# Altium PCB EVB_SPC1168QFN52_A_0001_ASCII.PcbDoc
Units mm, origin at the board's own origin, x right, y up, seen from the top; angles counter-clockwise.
Board outline 65.1 x 66.6 mm, 2 copper layers (Top Layer, Bottom Layer); 106 components, 105 nets, 333 pads, 121 vias.
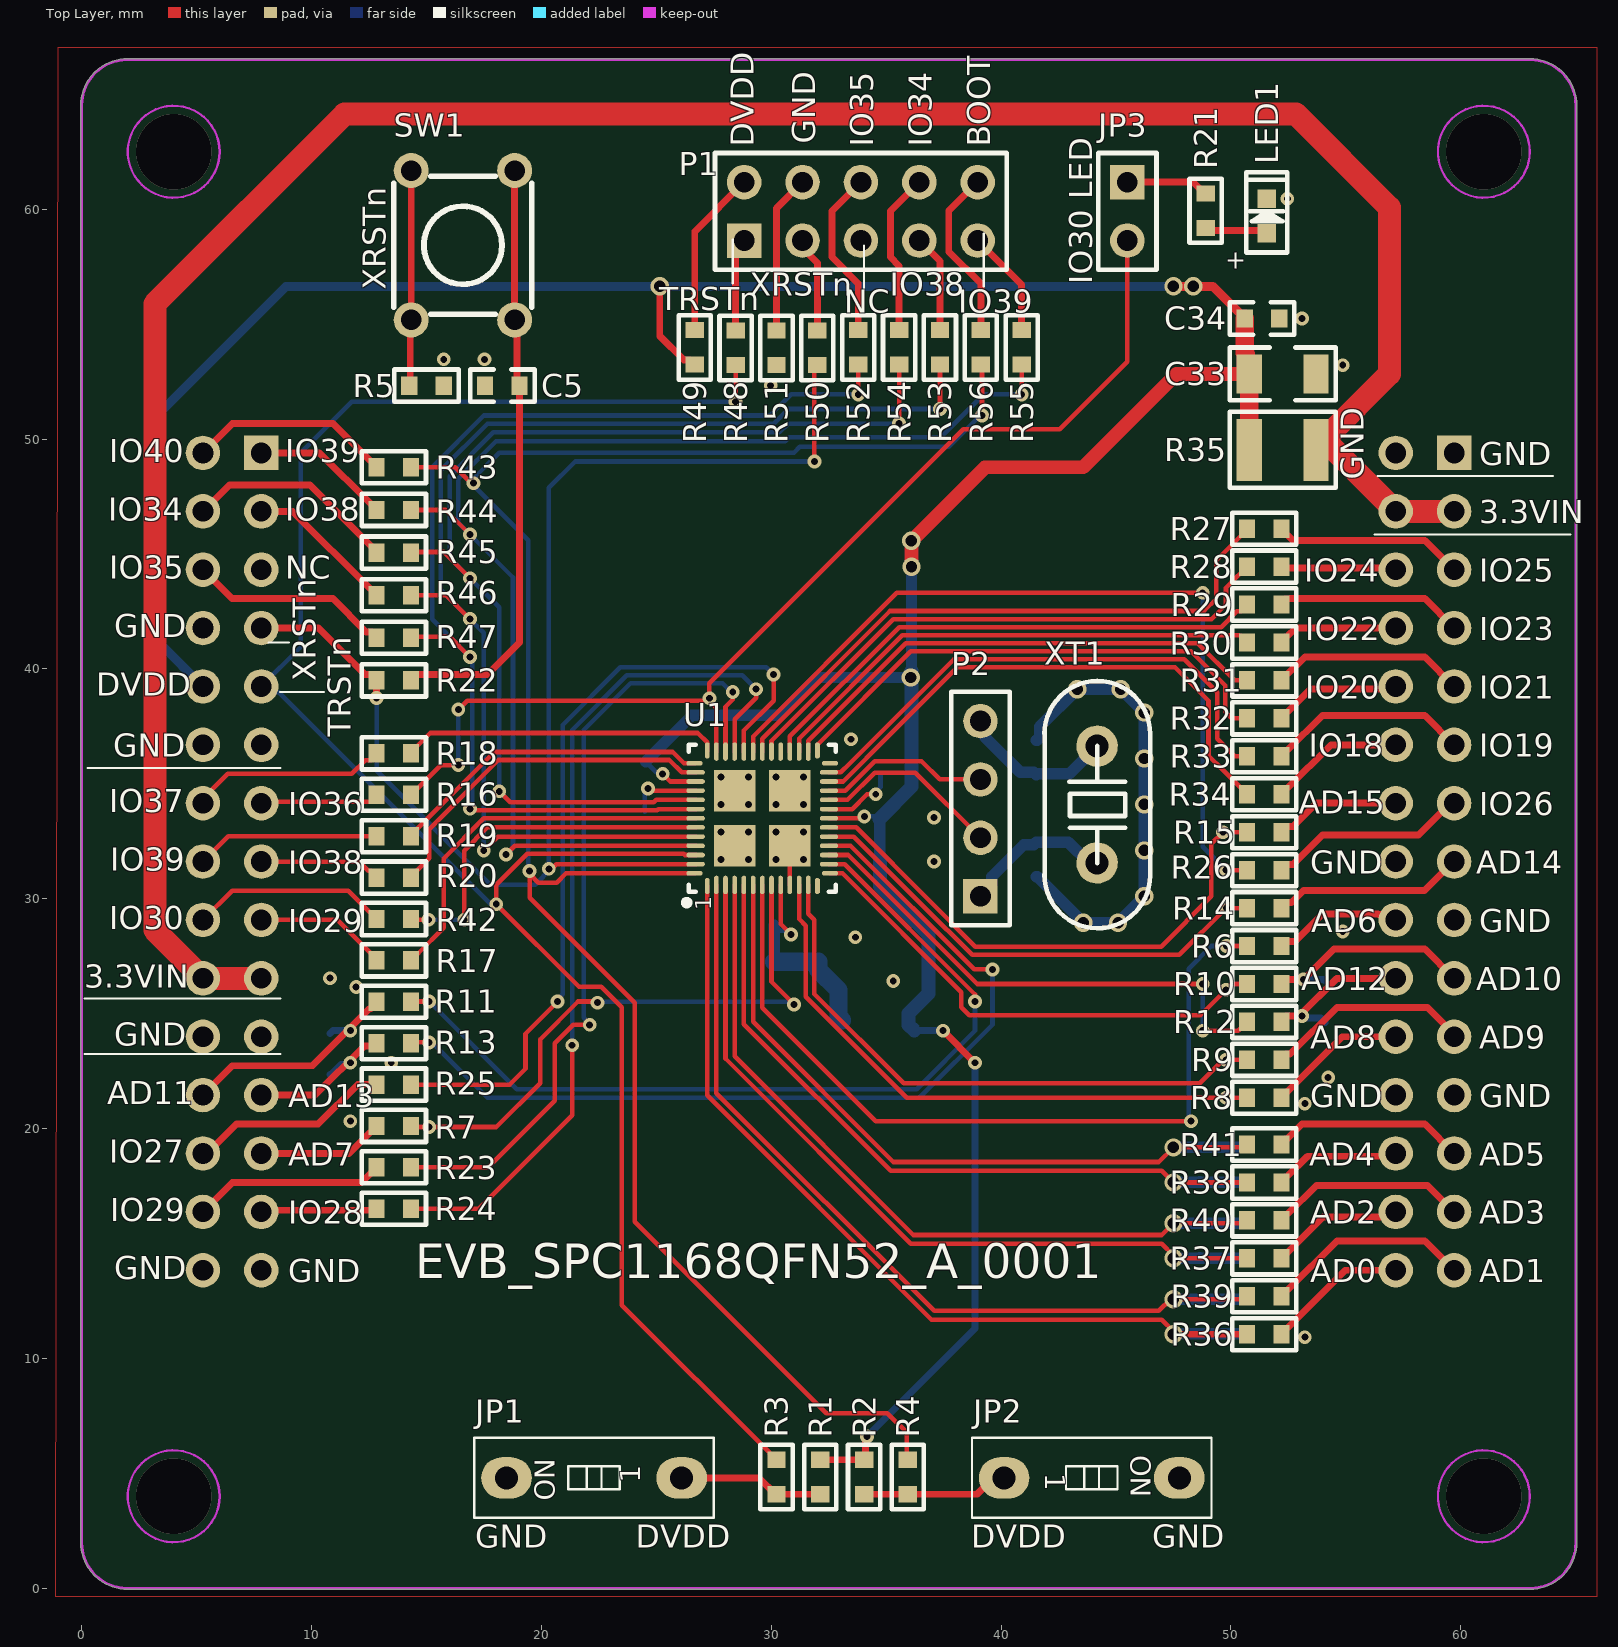
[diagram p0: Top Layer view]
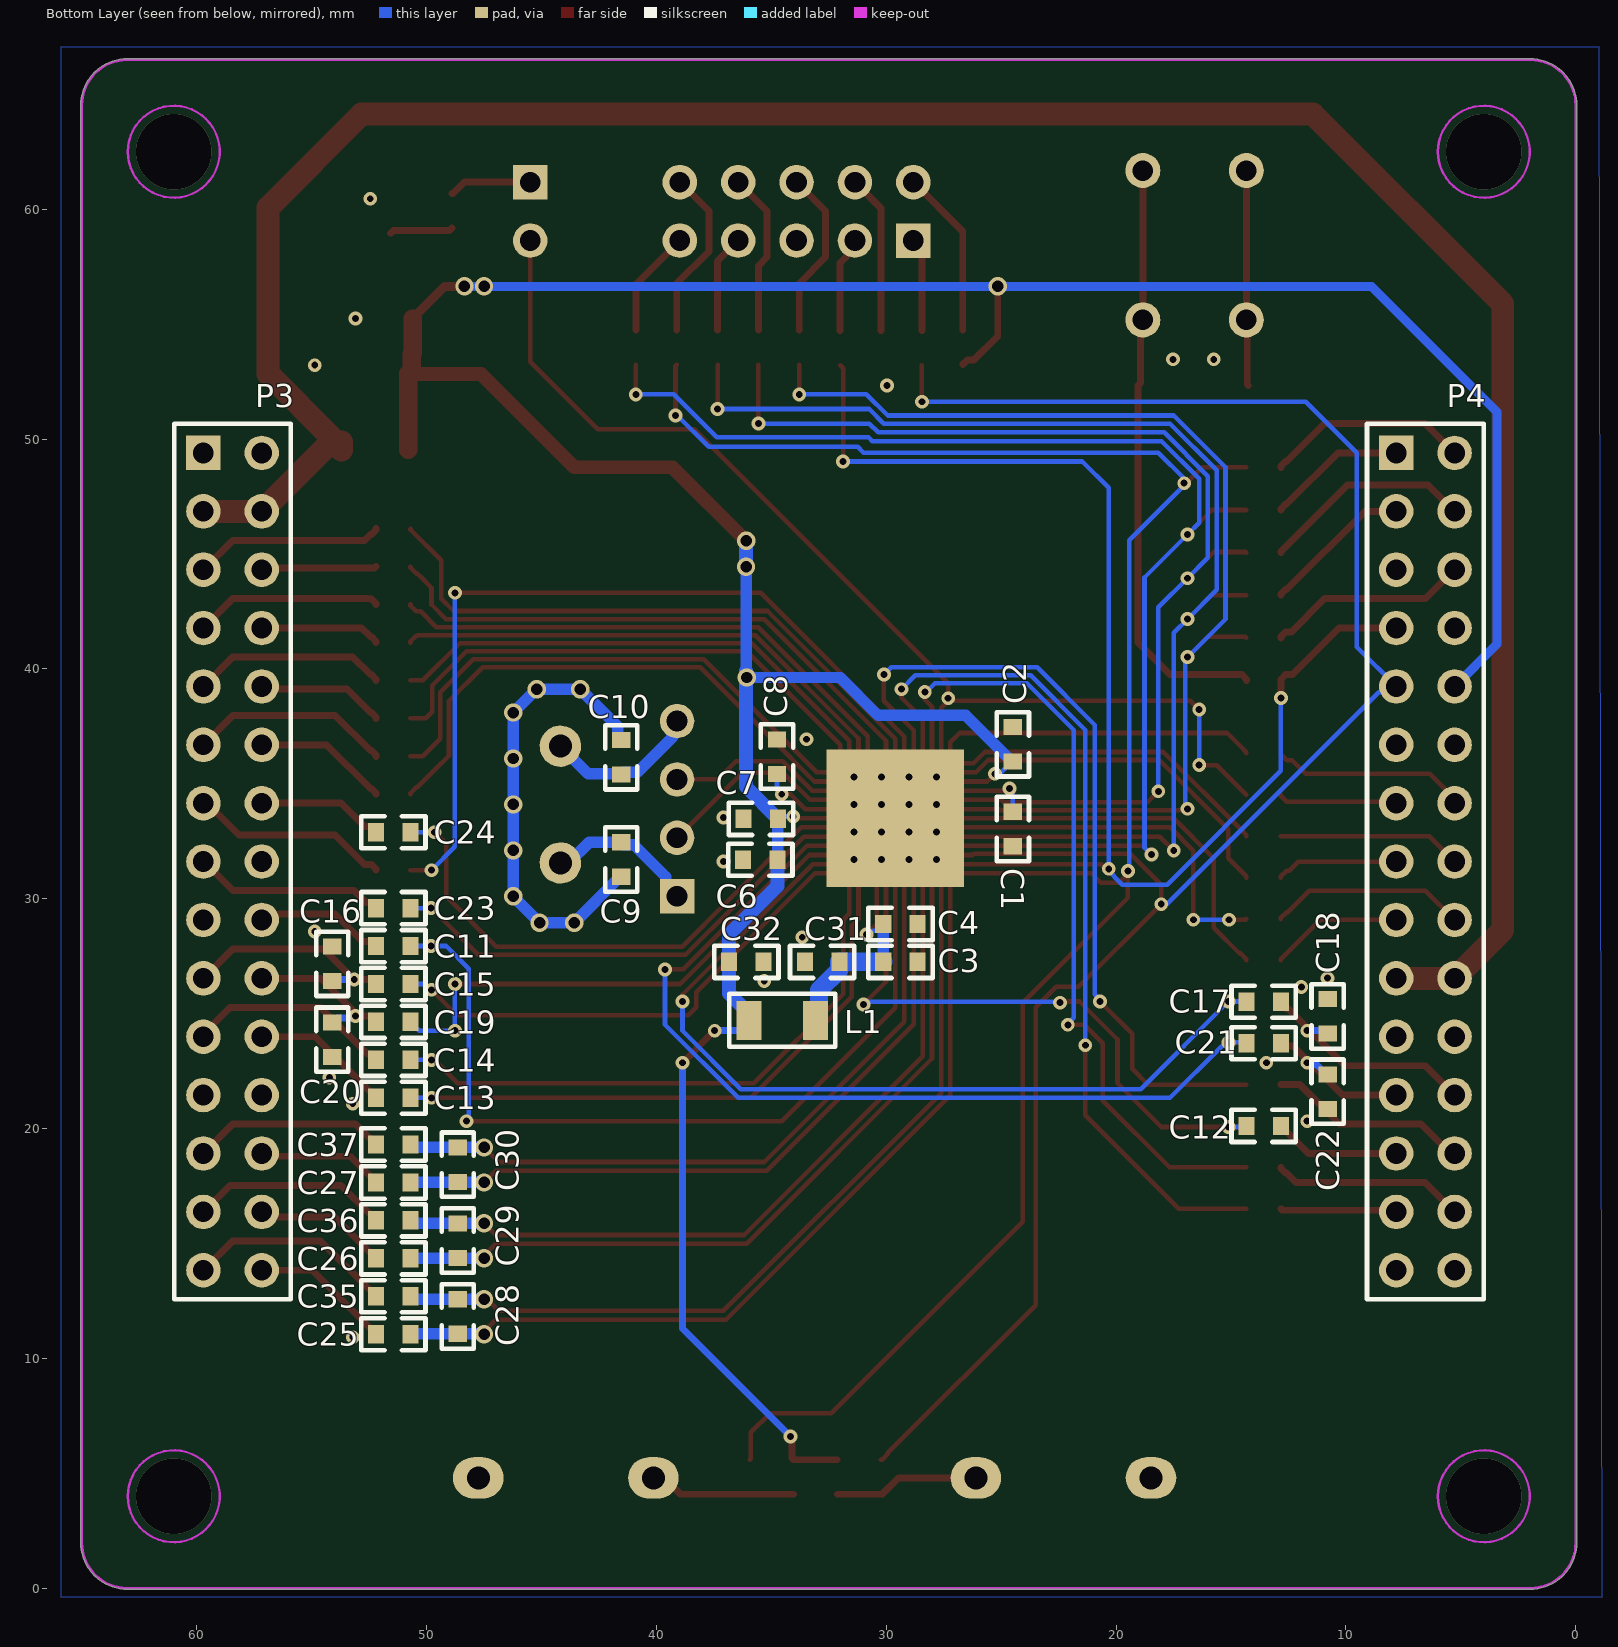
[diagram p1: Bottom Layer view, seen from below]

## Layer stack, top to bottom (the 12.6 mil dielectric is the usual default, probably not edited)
Top Solder: solder mask 0.0102, Solder Resist, Dk 3.5
Top Layer: signal copper 0.0356
Dielectric 1: dielectric 0.32, FR-4, Dk 4.8
Bottom Layer: signal copper 0.0356
Bottom Solder: solder mask 0.0102, Solder Resist, Dk 3.5

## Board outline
-0.05,2 ccw(c2,2) 2,-0.05 ccw(c2,0) 2.016,-0.048 ccw(c2.032,0) 2.032,-0.05 62.992,-0.05 ccw(c62.992,0) 62.996,-0.05 ccw(c63,0) 63,-0.05 ccw(c63,2) 65.05,2 ccw(c65,2) 65.05,2.004 ccw(c65,2.008) 65.05,2.008 65.05,64.5 ccw(c63,64.5) 63,66.55 2,66.55 ccw(c2,64.5) -0.05,64.5 -0.05,2.032 ccw(c0,2.032) -0.048,2.016 ccw(c0,2)

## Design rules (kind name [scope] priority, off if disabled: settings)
AssemblyTestPointUsage [All] p0: scope1count=1 scope1_0_kind=Board scope1_0_value=Board scope2count=1 scope2_0_kind=Board scope2_0_value=Board commentlength=0
AssemblyTestpoint [All] p0: scope1count=1 scope1_0_kind=Board scope1_0_value=Board scope2count=1 scope2_0_kind=Board scope2_0_value=Board commentlength=0
Clearance [All] p0: scope1count=1 scope1_0_kind=Board scope1_0_value=Board scope2count=1 scope2_0_kind=Board scope2_0_value=Board commentlength=0 gap=0.2
Clearance [All] p1: gap=0.2 ignorepadtopadclearanceinfootprint=FALSE except(0: Arc-Hole Track-Hole SMDPad-Hole THPad-Hole Via-Hole Fill-Hole Poly-Hole Region-Hole Text-Hole; 0.15: Arc-Arc Arc-Track Track-Track)
ComponentClearance [All] p0: scope1count=1 scope1_0_kind=Board scope1_0_value=Board scope2count=1 scope2_0_kind=Board scope2_0_value=Board commentlength=0 gap=0.254 collisioncheckmode=3
DiffPairsRouting [All] p0: scope1count=1 scope1_0_kind=Board scope1_0_value=Board scope2count=1 scope2_0_kind=Board scope2_0_value=Board commentlength=0
FabricationTestPointUsage [All] p0: scope1count=1 scope1_0_kind=Board scope1_0_value=Board scope2count=1 scope2_0_kind=Board scope2_0_value=Board commentlength=0 valid=0 allowmultiple=FALSE
FabricationTestpoint [All] p0: scope1count=1 scope1_0_kind=Board scope1_0_value=Board scope2count=1 scope2_0_kind=Board scope2_0_value=Board commentlength=0 side=3 testpointundercomponent=TRUE minsize=1.016 maxsize=2.54 preferedsize=1.524 minholesize=0 maxholesize=1.016 preferedholesize=0.813 testpointgrid=0.025
FanoutControl Fanout_BGA [All] p0 off: scope1count=1 scope1_0_kind=Board scope1_0_value=Board scope2count=1 scope2_0_kind=Board scope2_0_value=Board commentlength=69 // Protel DXP Scope 1 Expression Was: IsBGA   Fanout_BGA (Default Rule)
FanoutControl Fanout_LCC [All] p0 off: scope1count=1 scope1_0_kind=Board scope1_0_value=Board scope2count=1 scope2_0_kind=Board scope2_0_value=Board commentlength=69 // Protel DXP Scope 1 Expression Was: IsLCC   Fanout_LCC (Default Rule)
FanoutControl Fanout_SOIC [All] p0 off: scope1count=1 scope1_0_kind=Board scope1_0_value=Board scope2count=1 scope2_0_kind=Board scope2_0_value=Board commentlength=71 // Protel DXP Scope 1 Expression Was: IsSOIC   Fanout_SOIC (Default Rule)
FanoutControl Fanout_Small [All] p0 off: scope1count=1 scope1_0_kind=Board scope1_0_value=Board scope2count=1 scope2_0_kind=Board scope2_0_value=Board commentlength=84 // Protel DXP Scope 1 Expression Was: (CompPinCount < 5)   Fanout_Small (Default Rule)
FanoutControl Fanout_Default [All] p0: scope1count=1 scope1_0_kind=Board scope1_0_value=Board scope2count=1 scope2_0_kind=Board scope2_0_value=Board commentlength=30 // Fanout_Default (Default Rule)
Height [All] p0: scope1count=1 scope1_0_kind=Board scope1_0_value=Board scope2count=1 scope2_0_kind=Board scope2_0_value=Board commentlength=0
HoleSize [All] p0: scope1count=1 scope1_0_kind=Board scope1_0_value=Board scope2count=1 scope2_0_kind=Board scope2_0_value=Board commentlength=0 absolutevalues=TRUE maxlimit=2.54 minlimit=0.025 maxpercent=80.000 minpercent=20.000
HoleToHoleClearance [All] p0: scope1count=1 scope1_0_kind=Board scope1_0_value=Board scope2count=1 scope2_0_kind=Board scope2_0_value=Board commentlength=0
LayerPairs [All] p0: scope1count=1 scope1_0_kind=Board scope1_0_value=Board scope2count=1 scope2_0_kind=Board scope2_0_value=Board commentlength=0 enforce=TRUE
MinimumSolderMaskSliver [All] p0: scope1count=1 scope1_0_kind=Board scope1_0_value=Board scope2count=1 scope2_0_kind=Board scope2_0_value=Board commentlength=0
NetAntennae [All] p0: scope1count=1 scope1_0_kind=Board scope1_0_value=Board scope2count=1 scope2_0_kind=Board scope2_0_value=Board commentlength=0
PasteMaskExpansion [All] p0: scope1count=1 scope1_0_kind=Board scope1_0_value=Board scope2count=1 scope2_0_kind=Board scope2_0_value=Board commentlength=0 expansion=0
PlaneClearance [All] p0: scope1count=1 scope1_0_kind=Board scope1_0_value=Board scope2count=1 scope2_0_kind=Board scope2_0_value=Board commentlength=0 clearance=0.508
PlaneConnect [All] p0: scope1count=1 scope1_0_kind=Board scope1_0_value=Board scope2count=1 scope2_0_kind=Board scope2_0_value=Board commentlength=0 planeconnectstyle=Direct reliefexpansion=0.508 reliefentries=4 reliefconductorwidth=0.254 reliefairgap=0.254
PlaneConnect [All] p1: planeconnectstyle=Direct reliefexpansion=0.508 reliefentries=4 reliefconductorwidth=0.254 reliefairgap=0.254
PolygonConnect [All] p0: scope1count=1 scope1_0_kind=Board scope1_0_value=Board scope2count=1 scope2_0_kind=Board scope2_0_value=Board commentlength=0 connectstyle=Direct reliefconductorwidth=0.254 reliefentries=4 polygonreliefangle="90 Angle"
PolygonConnect [All] p1: connectstyle=Direct reliefconductorwidth=0.254 reliefentries=4 polygonreliefangle="90 Angle" airgapwidth=0.254
RoutingCorners [All] p0: scope1count=1 scope1_0_kind=Board scope1_0_value=Board scope2count=1 scope2_0_kind=Board scope2_0_value=Board commentlength=0 cornerstyle=45-Degree minsetback=2.54 maxsetback=2.54
RoutingLayers [All] p0: scope1count=1 scope1_0_kind=Board scope1_0_value=Board scope2count=1 scope2_0_kind=Board scope2_0_value=Board commentlength=0 top layer=Automatic bottom layer=Automatic
RoutingPriority [All] p0: scope1count=1 scope1_0_kind=Board scope1_0_value=Board scope2count=1 scope2_0_kind=Board scope2_0_value=Board commentlength=0
RoutingTopology [All] p0: scope1count=1 scope1_0_kind=Board scope1_0_value=Board scope2count=1 scope2_0_kind=Board scope2_0_value=Board commentlength=0 topology=Shortest
RoutingVias [All] p0: scope1count=1 scope1_0_kind=Board scope1_0_value=Board scope2count=1 scope2_0_kind=Board scope2_0_value=Board commentlength=0 holewidth=0.711 width=1.27 viastyle="Through Hole" minholewidth=0.711 minwidth=1.27 maxholewidth=4 maxwidth=4
RoutingVias [All] p1: holewidth=0.711 width=1.27 viastyle="Through Hole" minholewidth=0.711 minwidth=1.27 maxholewidth=4 maxwidth=4
ShortCircuit [All] p0: scope1count=1 scope1_0_kind=Board scope1_0_value=Board scope2count=1 scope2_0_kind=Board scope2_0_value=Board commentlength=0 allowed=FALSE
SilkToBoardRegionClearance [All] p0: scope1count=1 scope1_0_kind=Board scope1_0_value=Board scope2count=1 scope2_0_kind=Board scope2_0_value=Board commentlength=0
SilkToSilkClearance [All] p0: scope1count=1 scope1_0_kind=Board scope1_0_value=Board scope2count=1 scope2_0_kind=Board scope2_0_value=Board commentlength=0
SilkToSolderMaskClearance [All] p0 off: scope1count=1 scope1_0_kind=Board scope1_0_value=Board scope2count=1 scope2_0_kind=Board scope2_0_value=Board commentlength=44 // Protel DXP Scope 1 Expression Was: IsPad
SolderMaskExpansion [All] p0: scope1count=1 scope1_0_kind=Board scope1_0_value=Board scope2count=1 scope2_0_kind=Board scope2_0_value=Board commentlength=0 expansion=0.102
SolderMaskExpansion [All] p1: expansion=0.102 istentingtop=FALSE
UnRoutedNet [All] p0: scope1count=1 scope1_0_kind=Board scope1_0_value=Board scope2count=1 scope2_0_kind=Board scope2_0_value=Board commentlength=0
UnpouredPolygon [All] p0: scope1count=1 scope1_0_kind=Board scope1_0_value=Board scope2count=1 scope2_0_kind=Board scope2_0_value=Board commentlength=0
Width [All] p0: scope1count=1 scope1_0_kind=Board scope1_0_value=Board scope2count=1 scope2_0_kind=Board scope2_0_value=Board commentlength=0 maxlimit=3 minlimit=0.15 preferedwidth=0.254
Width [All] p1: maxlimit=3 minlimit=0.15 preferedwidth=0.254 minimp=50.000000 maximp=50.000000 favimp=50.000000
29 further rules are at their usual default settings.

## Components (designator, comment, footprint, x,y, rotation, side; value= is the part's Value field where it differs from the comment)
C1 "100nF" 0603C 24.487,32.282 r90 bottom
C2 "100nF" 0603C 24.487,37.465 r270 bottom
C3 "4.7uF" 0603C 28.631,27.249 r0 bottom
C4 "100nF" 0603C 28.631,28.9 r0 bottom
C5 "1uF" 0603C 17.55,52.324 r0 top
C6 "4.7uF" 0603C 36.227,31.694 r180 bottom
C7 "100nF" 0603C 36.203,33.472 r180 bottom
C8 "2.2uF" 0603C 34.753,36.933 r270 bottom
C9 "20pF" 0603C 41.529,30.956 r90 bottom
C10 "20pF" 0603C 41.529,36.901 r270 bottom
C11 "100pF" 0603C 50.697,27.94 r0 bottom
C12 "100pF" 0603C 14.327,20.112 r180 bottom
C13 "100pF" 0603C 50.697,21.336 r0 bottom
C14 "100pF" 0603C 50.697,22.987 r0 bottom
C15 "100pF" 0603C 50.697,26.289 r0 bottom
C16 "100pF" 0603C 54.102,27.916 r270 bottom
C17 "100pF" 0603C 14.327,25.515 r180 bottom
C18 "100pF" 0603C 10.795,25.63 r270 bottom
C19 "100pF" 0603C 50.697,24.638 r0 bottom
C20 "100pF" 0603C 54.102,23.114 r90 bottom
C21 "100pF" 0603C 14.327,23.714 r180 bottom
C22 "100pF" 0603C 10.795,20.852 r90 bottom
C23 "100pF" 0603C 50.697,29.591 r0 bottom
C24 "100pF" 0603C 50.697,32.893 r0 bottom
C25 "100pF" 0603C 50.697,11.049 r0 bottom
C26 "100pF" 0603C 50.697,14.351 r0 bottom
C27 "100pF" 0603C 50.697,17.653 r0 bottom
C28 "22pF" 0603C 48.641,12.573 r270 bottom
C29 "22pF" 0603C 48.641,15.875 r270 bottom
C30 "22pF" 0603C 48.641,19.177 r270 bottom
C31 "100nF" 0603C 33.536,27.249 r180 bottom
C32 "100nF" 0603C 35.338,27.249 r0 bottom
C33 "47uF" 1206C 53.7,52.832 r180 top
C34 "100nF" 0603C 52.1,55.245 r180 top
C35 "100pF" 0603C 52.197,12.7 r180 bottom
C36 "100pF" 0603C 52.197,16.002 r180 bottom
C37 "100pF" 0603C 52.197,19.304 r180 bottom
JP1 "DSIC01LH-P" Switch_3.5*10.4 26.1,4.8 r0 top
JP2 "DSIC01LH-P" Switch_3.5*10.4 40.13,4.8 r180 top
JP3 "Jumper" HDR1X2 45.49,61.175 r270 top locked
L1 "1.5uH" 1206L 33.073,24.709 r0 bottom
LED1 "" LED0603 51.562,58.952 r90 top
P1 "Header 5X2" HDR2X5 28.82,58.635 r0 top locked
P2 "Header 4" HDR1X4 39.1,30.11 r90 top locked
P3 "Header 15X2" HDR2X15 59.71,49.395 r270 bottom locked
P4 "Header 15X2" HDR2X15 7.81,49.395 r270 bottom locked
R1 "2K" 0603R 32.131,5.588 r270 top
R2 "2K" 0603R 34.036,5.588 r270 top
R3 "2K" 0603R 30.226,4.088 r90 top
R4 "2K" 0603R 35.941,4.088 r90 top
R5 "100R" 0603R 14.248,52.324 r0 top
R6 "100R" 0603R 50.697,27.94 r0 top
R7 "100R" 0603R 14.327,20.112 r180 top
R8 "100R" 0603R 50.697,21.336 r0 top
R9 "100R" 0603R 50.697,22.987 r0 top
R10 "100R" 0603R 50.697,26.289 r0 top
R11 "100R" 0603R 14.327,25.515 r180 top
R12 "100R" 0603R 50.697,24.638 r0 top
R13 "100R" 0603R 14.327,23.714 r180 top
R14 "100R" 0603R 50.697,29.591 r0 top
R15 "100R" 0603R 50.697,32.893 r0 top
R16 "100R" 0603R 14.327,34.521 r180 top
R17 "100R" 0603R 14.327,27.317 r180 top
R18 "100R" 0603R 14.327,36.322 r180 top
R19 "100R" 0603R 14.327,32.72 r180 top
R20 "100R" 0603R 14.327,30.919 r180 top
R21 "3.3K" 0603R 48.895,60.682 r270 top
R22 "4.7K" 0603R 14.327,39.497 r180 top
R23 "100R" 0603R 14.327,18.311 r180 top
R24 "100R" 0603R 14.327,16.51 r180 top
R25 "100R" 0603R 14.327,21.913 r180 top
R26 "100R" 0603R 50.697,31.242 r0 top
R27 "100R" 0603R 50.697,46.101 r0 top
R28 "100R" 0603R 50.697,44.45 r0 top
R29 "100R" 0603R 50.697,42.799 r0 top
R30 "100R" 0603R 50.697,41.148 r0 top
R31 "100R" 0603R 50.697,39.497 r0 top
R32 "100R" 0603R 50.697,37.846 r0 top
R33 "100R" 0603R 50.697,36.195 r0 top
R34 "100R" 0603R 50.697,34.544 r0 top
R35 "0.1R" 1210R 50.8,49.53 r0 top
R36 "100R" 0603R 52.197,11.049 r180 top
R37 "100R" 0603R 52.197,14.351 r180 top
R38 "100R" 0603R 52.197,17.653 r180 top
R39 "100R" 0603R 52.197,12.7 r180 top
R40 "100R" 0603R 52.197,16.002 r180 top
R41 "100R" 0603R 52.197,19.304 r180 top
R42 "100R" 0603R 14.327,29.118 r180 top
R43 "100R" 0603R 14.327,48.768 r180 top
R44 "100R" 0603R 12.827,46.914 r0 top
R45 "100R" 0603R 14.327,45.06 r180 top
R46 "100R" 0603R 12.827,43.205 r0 top
R47 "100R" 0603R 14.327,41.351 r180 top
R48 "100R" 0603R 28.448,53.213 r90 top
R49 "100R" 0603R 26.67,54.737 r270 top
R50 "100R" 0603R 32.004,53.213 r90 top
R51 "100R" 0603R 30.226,54.713 r270 top
R52 "100R" 0603R 33.782,54.737 r270 top
R53 "100R" 0603R 37.338,53.237 r90 top
R54 "100R" 0603R 35.56,54.737 r270 top
R55 "100R" 0603R 40.894,53.237 r90 top
R56 "100R" 0603R 39.116,54.737 r270 top
SW1 "插件按键6*6*5" Key_6*6 18.833,61.681 r0 top locked
U1 "SPC1168QFN52" QFN-52-0.4 28.408,32.3 r90 top locked
XT1 "32MHz" XT-HI 44.176,34.095 r90 top locked
? "Comment" 旋智标识8*3.5 35.941,16.256 r0 top

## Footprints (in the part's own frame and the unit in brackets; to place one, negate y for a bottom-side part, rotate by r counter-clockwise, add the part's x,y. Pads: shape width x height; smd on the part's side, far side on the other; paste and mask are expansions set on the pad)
0603C [mm]
  rect 0.7x0.8 smd: 1(0,0) 2(1.5,0)
  silkscreen extent -0.65,-0.7 2.15,0.7
0603R [mm]
  rect 0.7x0.8 smd: 1(0,0) 2(1.5,0)
  silkscreen extent -0.65,-0.7 2.15,0.7
1206C [mm]
  rect 1.1x1.7 smd: 1(0,0) 2(2.9,0)
  silkscreen extent -0.85,-1.15 3.75,1.15
1206L [mm]
  rect 1.1x1.7 smd: 1(0,0) 2(2.9,0)
  silkscreen extent -0.85,-1.15 3.75,1.15
1210R [mm]
  rect 1.1x2.7 smd: 1(0,0) 2(2.9,0)
  silkscreen extent -0.85,-1.65 3.75,1.65
HDR1X2 [mm] "Connector; Header; 2 Position"
  rect 1.5x1.5 hole 0.9: 1(0,0)
  round 1.5 hole 0.9: 2(2.54,0)
  silkscreen extent -1.27,-1.27 3.81,1.27
HDR1X4 [mm] "Connector; Header; 4 Position"
  rect 1.5x1.5 hole 0.9: 1(0,0)
  round 1.5 hole 0.9: 2(2.54,0) 3(5.08,0) 4(7.62,0)
  silkscreen extent -1.27,-1.27 8.89,1.27
HDR2X5 [mm] "Connector; Header; 5x2 Position"
  rect 1.5x1.5 hole 0.9: 1(0,0)
  round 1.5 hole 0.9: 2(0,2.54) 3(2.54,0) 4(2.54,2.54) 5(5.08,0) 6(5.08,2.54) 7(7.62,0) 8(7.62,2.54) 9(10.16,0) 10(10.16,2.54)
  silkscreen extent -1.27,-1.27 11.43,3.81
HDR2X15 [mm] "Connector; Header; 15x2 Position"
  rect 1.5x1.5 hole 0.9: 1(0,0)
  round 1.5 hole 0.9: 2(0,2.54) 3(2.54,0) 4(2.54,2.54) 5(5.08,0) 6(5.08,2.54) 7(7.62,0) 8(7.62,2.54) 9(10.16,0) 10(10.16,2.54) 11(12.7,0) 12(12.7,2.54) 13(15.24,0) 14(15.24,2.54) 15(17.78,0) 16(17.78,2.54) 17(20.32,0) 18(20.32,2.54) 19(22.86,0) 20(22.86,2.54) 21(25.4,0) 22(25.4,2.54) 23(27.94,0) 24(27.94,2.54) 25(30.48,0) 26(30.48,2.54) 27(33.02,0) 28(33.02,2.54) 29(35.56,0) 30(35.56,2.54)
  silkscreen extent -1.27,-1.27 36.83,3.81
Key_6*6 [mil]
  round 60 hole 35: 1(0,-255.9) 1(0,0) 2(-177.16,-255.9) 2(-177.16,0)
  silkscreen extent -207,-246 30,-10
LED0603 [mm]
  rect 0.8x0.8 smd: A(0,0) K(1.5,0)
  silkscreen extent -0.84,-0.89 2.66,0.89
QFN-52-0.4 [mm] "P0.4,6*6mm"
  rect 1.8x1.8 smd: 0(0,0) 0(0,-2.4) 0(2.4,-2.4) 0(2.4,0)
  rect 6x6 smd far side: 0(1.2,-1.2)
  oct 0.7x0.2 smd: 1(-1.75,1.2) 13(-1.75,-3.6) 27(4.15,-3.6) 39(4.15,1.2)
  oval 0.8x0.2 smd: 2(-1.7,0.8) 3(-1.7,0.4) 4(-1.7,0) 5(-1.7,-0.4) 6(-1.7,-0.8) 7(-1.7,-1.2) 8(-1.7,-1.6) 9(-1.7,-2) 10(-1.7,-2.4) 11(-1.7,-2.8) 12(-1.7,-3.2) 28(4.1,-3.2) 29(4.1,-2.8) 30(4.1,-2.4) 31(4.1,-2) 32(4.1,-1.6) 33(4.1,-1.2) 34(4.1,-0.8) 35(4.1,-0.4) 36(4.1,0) 37(4.1,0.4) 38(4.1,0.8)
  oct 0.2x0.7 smd: 14(-1.2,-4.15) 26(3.6,-4.15) 40(3.6,1.75) 52(-1.2,1.75)
  oval 0.2x0.8 smd: 15(-0.8,-4.1) 16(-0.4,-4.1) 17(0,-4.1) 18(0.4,-4.1) 19(0.8,-4.1) 20(1.2,-4.1) 21(1.6,-4.1) 22(2,-4.1) 23(2.4,-4.1) 24(2.8,-4.1) 25(3.2,-4.1) 41(3.2,1.7) 42(2.8,1.7) 43(2.4,1.7) 44(2,1.7) 45(1.6,1.7) 46(1.2,1.7) 47(0.8,1.7) 48(0.4,1.7) 49(0,1.7) 50(-0.4,1.7) 51(-0.8,1.7)
  silkscreen extent -2.59,-4.4 4.4,2.21
Switch_3.5*10.4 [mm]
  oval 2.2x1.8 hole 1: 1(0,0) 2(-7.62,0)
  silkscreen extent -9.02,-1.74 1.4,1.74
XT-HI [mm]
  round 1.8 hole 1: 1(-2.54,0) 2(2.54,0)
  silkscreen extent -5.38,-2.31 5.38,2.29
旋智标识8*3.5 [mm]

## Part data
C1 C2 C3 C4 C5 C6 C7 C8 C9 C10 C11 C12 C13 C14 C15 C16 C17 C18 C19 C20 C21 C22 C23 C24 C25 C26 C27 C28 C29 C30 C31 C32 C33 C34 C35 C36 C37: library part Capacitor, "无极性电容"
JP1 JP2: library part SW-2
JP3: "Jumper Wire"
L1: library part "Magnetic Beads", "磁珠"
LED1: library part LED, "发光二极管"
P1: "Header, 5-Pin, Dual row"
P2: "Header, 4-Pin"
P3 P4: "Header, 15-Pin, Dual row"
R1 R2 R3 R4 R5 R6 R7 R8 R9 R10 R11 R12 R13 R14 R15 R16 R17 R18 R19 R20 R21 R22 R23 R24 R25 R26 R27 R28 R29 R30 R31 R32 R33 R34 R35 R36 R37 R38 R39 R40 R41 R42 R43 R44 R45 R46 R47 R48 R49 R50 R51 R52 R53 R54 R55 R56: library part Resistance, "电阻"
SW1: library part SW-PB, "Switch"
XT1: library part CRYSTAL-2P

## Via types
v1: diameter 0.6, hole 0.3, Top Layer to Bottom Layer, tented both sides, 80 vias
v2: diameter 0.8, hole 0.5, Top Layer to Bottom Layer, tented both sides, 21 vias
v3: diameter 0.6, hole 0.3, Top Layer to Bottom Layer, 16 vias
v4: diameter 3.3, hole 3.3, Top Layer to Bottom Layer, tented both sides, 4 vias

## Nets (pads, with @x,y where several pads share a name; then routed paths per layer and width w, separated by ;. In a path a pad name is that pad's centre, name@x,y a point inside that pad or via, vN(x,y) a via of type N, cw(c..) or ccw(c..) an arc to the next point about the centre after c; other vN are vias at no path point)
3.3VIN: P3.3 P3.4 P4.19 P4.20 R35.2 | length 110.1
  Top Layer w1: P4.19 P4.20 3.175,28.63 3.175,55.88 11.43,64.135 52.832,64.135 56.896,60.071 56.896,52.832 54.098,50.034 54.098,49.927 P3.4 P3.3 ; R35.2 R35.2@53.7,49.877
ADC6: C11.1 R6.1 U1.7 | length 36.5
  Top Layer w0.2: U1.7 29.608,25.256 34.544,20.32 v1(48.26,20.32) ; v1(49.806,27.94) R6.1
  Bottom Layer w0.2: v1(48.26,20.32) 48.168,20.412 48.168,26.959 49.149,27.94 C11.1
ADC7: C12.1 R7.1 U1.8 | length 26.6
  Top Layer w0.2: R7.1 14.373,20.066 v1(15.113,20.066) 18.034,20.066 19.939,21.971 19.939,23.876 21.59,25.527 22.392,25.527 v1(22.444,25.475) ; U1.8 30.008,26.38 v1(30.988,25.4)
  Bottom Layer w0.2: C12.1 14.373,20.066 v1(15.113,20.066) ; v1(22.444,25.475) 22.48,25.512 30.876,25.512 v1(30.988,25.4)
ADC8: C13.1 R8.1 U1.11 | length 26.9
  Top Layer w0.2: U1.11 31.208,29.117 31.496,28.829 31.496,25.741 35.901,21.336 v1(49.784,21.336) R8.1
  Bottom Layer w0.2: v1(49.784,21.336) C13.1
ADC9: C14.1 R9.1 U1.12 | length 26.6
  Top Layer w0.2: U1.12 31.608,29.352 31.877,29.083 31.877,25.854 35.76,21.971 48.641,21.971 49.657,22.987 v1(49.784,22.987) R9.1
  Bottom Layer w0.2: v1(49.784,22.987) C14.1
ADC10: C15.1 R10.1 U1.14 | length 22.7
  Top Layer w0.2: U1.14 33.099,31.1 38.262,25.937 38.262,25.278 38.613,24.927 48.676,24.927 v1(49.784,26.035) 50.038,26.289 R10.1
  Bottom Layer w0.2: v1(49.784,26.035) 49.832,26.035 50.086,26.289 C15.1
ADC11: C17.1 R11.1 U1.15 | length 38.2
  Top Layer w0.2: R11.1 14.339,25.527 v1(15.113,25.527) ; U1.15 33.194,31.5 38.862,25.832 v1(38.862,25.527)
  Bottom Layer w0.2: C17.1 14.339,25.527 v1(15.113,25.527) 18.923,21.717 36.322,21.717 38.862,24.257 v1(38.862,25.527)
ADC12: C19.1 R12.1 U1.16 | length 25.4
  Top Layer w0.2: U1.16 33.352,31.9 38.963,26.289 v1(48.768,26.289) ; 49.403,24.257 v1(48.768,24.257) 50.316,24.257 R12.1
  Bottom Layer w0.2: v1(48.768,26.289) v1(48.768,24.257) 50.316,24.257 C19.1
ADC13: C21.1 R13.1 U1.17 | length 40.2
  Top Layer w0.2: R13.1 14.362,23.749 v1(15.113,23.749) ; U1.17 33.447,32.3 38.823,26.924 v1(39.624,26.924)
  Bottom Layer w0.2: C21.1 14.362,23.749 v1(15.113,23.749) 15.221,23.749 15.382,23.588 15.401,23.588 17.653,21.336 36.436,21.336 39.624,24.524 v1(39.624,26.924)
ADC14: C23.1 R14.1 U1.18 | length 22.1
  Top Layer w0.2: U1.18 33.594,32.7 36.576,29.718 38.735,27.559 47.752,27.559 49.784,29.591 R14.1
  Bottom Layer w0.2: v1@49.784,29.591 C23.1
  other v1: 49.806,29.591
ADC15: C24.1 R15.1 U1.19 | length 24.8
  Top Layer w0.2: U1.19 33.689,33.1 36.926,29.863 38.88,27.909 46.959,27.909 49.149,30.099 49.149,32.385 v1(49.657,32.893) R15.1
  Bottom Layer w0.2: v1(49.657,32.893) C24.1
ADC_7: P4.25 R7.2 | length 5.5
  Top Layer w0.3: P4.25 11.63,18.915 12.577,19.862 12.627,19.862 12.827,20.062 R7.2
ADC_11: C18.2 P4.24 R11.2 | length 10.2
  Top Layer w0.3: P4.24 6.548,22.733 10.045,22.733 12.527,25.215 12.577,25.215 12.827,25.465 R11.2
  Bottom Layer w0.3: C18.2 10.922,24.257 v1(11.684,24.257)
ADC_13: C22.2 P4.23 R13.2 | length 7.1
  Top Layer w0.3: P4.23 10.152,21.455 12.294,23.597 12.71,23.597 R13.2
  Bottom Layer w0.3: C22.2 10.845,22.352 11.276,22.783 11.607,22.783 v1(11.684,22.86)
AVDD: C3.2 C4.2 C31.2 L1.1 U1.9 | length 9.8
  Top Layer w0.2: U1.9 30.408,28.901 v1(30.861,28.448)
  Bottom Layer w0.2: C4.2 30.131,28.85 30.381,28.6 30.601,28.6 30.753,28.448 v1(30.861,28.448)
  Bottom Layer w0.5: C3.2 C4.2@30.131,28.85
  Bottom Layer w0.8: C3.2 C31.2 32.036,26.911 32.923,26.024 32.923,24.859 L1.1
BOOT: R4.2 R43.1 R56.2 U1.52 | length 88.1
  Top Layer w0.2: R43.1 16.256,48.768 16.945,48.079 v1(17.037,48.079) ; v1(19.483,31.207) v1@19.483,31.082 ; U1.52 21.067,31.1 20.667,30.7 19.865,30.7 v1@19.483,31.082 ; R4.2 35.891,5.638 35.891,6.781 35.052,7.62 32.385,7.62 24.06,15.945 24.06,25.47 19.483,30.047 v1@19.483,31.082 ; R56.2 39.168,53.185 v1(39.168,51.019)
  Bottom Layer w0.2: v1@16.991,48.033 19.431,45.593 19.431,31.259 v1(19.483,31.207) ; v1(17.037,48.079) 17.02,48.096 17.02,48.262 18.161,49.403 30.988,49.403 31.242,49.657 37.719,49.657 39.081,51.019 v1(39.168,51.019)
DC_BUS: P3.18 R6.2 | length 5.7
  Top Layer w0.3: R6.2 52.197,27.943 52.397,28.143 52.781,28.143 53.975,29.337 56.394,29.337 56.427,29.305 56.94,29.305 P3.18
DIR: P3.11 R33.2 | length 8.8
  Top Layer w0.3: R33.2 52.197,36.245 52.397,36.445 52.447,36.445 53.975,37.973 58.432,37.973 P3.11
DVDD: C2.2 C6.2 C7.2 C32.2 C33.2 C34.2 L1.2 P4.10 R1.1 R2.1 R35.1 R49.2 U1.20 U1.42 | length 158
  Top Layer w0.2: v1(25.273,35.433) 25.606,35.1 U1.42 ; U1.20 33.754,33.5 33.758,33.504 33.972,33.504 v1(34.048,33.581)
  Top Layer w0.3: v2(25.146,56.642) 25.146,54.483 26.192,53.437 26.47,53.437 R49.2 ; R1.1 R2.1 34.106,5.658 34.106,6.547 v1(34.163,6.604) ; v1(37.465,24.257) v1(38.862,22.86)
  Top Layer w0.4: v2(47.498,56.642) v2(48.351,56.642) 49.203,56.642 50.4,55.445 50.45,55.445 50.6,55.295 C34.2
  Top Layer w0.6: v2(36.1,44.45) 36.1,45.561 v2(36.092,45.569) 39.291,48.768 43.561,48.768 47.625,52.832 C33.2
  Top Layer w0.8: C34.2 50.6,53.751 50.65,53.701 50.65,52.982 C33.2 R35.1
  Bottom Layer w0.2: C2.2 24.537,35.965 24.992,35.51 25.196,35.51 v1(25.273,35.433) ; v1(34.048,33.581) 34.594,33.581 C7.2
  Bottom Layer w0.3: v1(34.163,6.604) 38.862,11.303 v1(38.862,22.86) ; L1.2@36.223,24.257 v1(37.465,24.257)
  Bottom Layer w0.4: P4.10 3.429,41.076 3.429,51.181 8.89,56.642 v2(47.498,56.642) v2(48.351,56.642)
  Bottom Layer w0.5: C2.2@24.537,35.965 26.545,37.973 30.353,37.973 32.004,39.624 v2(36.068,39.624) ; C7.2 34.715,33.46 34.715,31.706 C6.2 ; v2@36.1,39.91 v2(36.1,44.45)
  Bottom Layer w0.6: C7.2 36.1,34.869 36.1,39.624 v2@36.1,39.91 ; C6.2 34.727,30.551 36.838,28.44 C32.2 36.838,25.874 35.973,25.009 L1.2 35.973,24.507 L1.2@36.223,24.257 ; v2(36.092,45.569) 36.1,45.561 v2(36.1,44.45)
GND: C1.1 C2.1 C3.1 C4.1 C5.1 C6.1 C7.1 C8.1 C9.1 C10.1 C11.2 C12.2 C13.2 C14.2 C15.2 C16.1 C17.2 C18.1 C19.2 C20.1 C21.2 C22.1 C23.2 C24.2 C25.2 C26.2 C27.2 C31.1 C32.1 C33.1 C34.1 C35.1 C36.1 C37.1 JP1.2 JP2.2 LED1.K P3.1 P3.2 P3.16 P3.17 P3.23 P3.24 P4.8 P4.11 P4.12 P4.21 P4.22 P4.29 P4.30 R5.2 R51.2 U1.0 U1.10 | length 22
  Top Layer w0.2: U1.10 U1.0@30.808,32.3
  Bottom Layer w0.5: C9.1 41.579,30.956 v2(43.579,28.956) v2(45.085,28.956) v2(46.228,30.099) v2(46.228,38.1) v2(45.212,39.116) v2(43.307,39.116) 41.679,37.488 41.679,37.001 41.579,36.901 C10.1
  other v1: 53.213,10.922 11.684,20.32 53.213,21.082 54.229,22.225 13.462,22.86 11.938,26.162 35.306,26.416 10.795,26.543 33.655,28.321 54.864,28.575 37.084,31.623 37.084,33.528 33.471,36.939 29.972,52.324 54.864,53.213 15.748,53.467 17.526,53.467 53.086,55.245 52.451,60.452
  other v2: 46.228,32.099 46.228,34.099 46.228,36.1
  other v3: 27.808,31.7 29.008,31.7 30.208,31.7 31.408,31.7 27.808,32.9 29.008,32.9 30.208,32.9 31.408,32.9 27.808,34.1 29.008,34.1 30.208,34.1 31.408,34.1 27.808,35.3 29.008,35.3 30.208,35.3 31.408,35.3
GPIO16: P2.2 U1.22 | length 8.3
  Top Layer w0.2: U1.22 33.315,34.3 34.496,35.481 36.269,35.481 P2.2
GPIO17: P2.3 U1.23 | length 7.5
  Top Layer w0.2: U1.23 33.22,34.7 34.502,35.983 36.534,35.983 37.327,35.19 P2.3
GPIO18: R34.1 U1.24 | length 24
  Top Layer w0.2: U1.24 33.125,35.1 33.751,35.726 34.505,36.48 38.092,40.067 47.563,40.067 49.022,38.608 49.022,36.219 49.657,35.584 50.397,34.844 50.447,34.844 50.697,34.594 R34.1
GPIO19: R33.1 U1.25 | length 23.2
  Top Layer w0.2: U1.25 33.03,35.5 33.401,35.871 37.947,40.417 47.975,40.417 49.403,38.989 49.403,36.957 50.165,36.195 R33.1
GPIO20: R32.1 U1.27 | length 22.5
  Top Layer w0.2: U1.27 32.008,36.7 36.075,40.767 48.26,40.767 49.753,39.274 49.753,38.131 50.038,37.846 R32.1
GPIO21: R31.1 U1.28 | length 22
  Top Layer w0.2: U1.28 31.608,36.874 35.851,41.117 37.294,41.117 48.545,41.117 50.165,39.497 R31.1
GPIO22: R30.1 U1.29 | length 22.1
  Top Layer w0.2: U1.29 31.208,36.969 35.706,41.467 36.641,41.467 50.378,41.467 50.397,41.448 50.447,41.448 50.697,41.198 R30.1
GPIO23: R29.1 U1.30 | length 23
  Top Layer w0.2: U1.30 30.808,37.064 35.561,41.817 49.576,41.817 50.258,42.499 50.447,42.499 50.697,42.749 R29.1
GPIO24: R28.1 U1.32 | length 24.8
  Top Layer w0.2: U1.32 30.008,36.866 35.309,42.167 49.152,42.167 49.784,42.799 49.784,43.537 50.225,43.978 50.397,44.15 50.447,44.15 50.697,44.4 R28.1
GPIO25: R27.1 U1.33 | length 26.4
  Top Layer w0.2: U1.33 29.608,36.961 35.164,42.517 48.827,42.517 49.368,43.058 49.368,44.722 50.697,46.051 R27.1
GPIO26: R26.1 U1.34 | length 36.2
  Top Layer w0.2: U1.34 29.208,37.056 35.459,43.307 v1(48.768,43.307) ; v1(49.784,31.242) R26.1
  Bottom Layer w0.2: v1(48.768,43.307) 48.768,32.258 v1(49.784,31.242)
GPIO27: P4.26 R25.2 | length 8.8
  Top Layer w0.3: P4.26 5.453,18.915 6.731,20.193 10.287,20.193 12.007,21.913 R25.2
GPIO28: P4.27 R24.2 | length 5.1
  Top Layer w0.3: P4.27 7.878,16.442 12.759,16.442 R24.2
GPIO29: P4.28 R23.2 | length 8.4
  Top Layer w0.3: P4.28 6.548,17.653 12.169,17.653 12.577,18.061 12.627,18.061 12.827,18.261 R23.2
GPIO30: JP3.2 R16.1 U1.38 | length 48.4
  Top Layer w0.2: R16.1 15.62,35.814 v1(16.383,35.814) ; v1(16.383,38.227) 16.764,38.608 v1@27.305,38.608 ; U1.38 27.608,38.305 v1@27.305,38.608 ; JP3.2 45.49,53.364 42.545,50.419 38.354,50.419 27.305,39.37 v1@27.305,38.608
  Bottom Layer w0.2: v1(16.383,35.814) v1(16.383,38.227)
  other v1: 27.305,38.723
GPIO31: R18.1 U1.39 | length 13.8
  Top Layer w0.2: R18.1 14.327,36.372 14.577,36.622 15.166,37.211 26.797,37.211 27.208,36.8 U1.39
GPIO32: R19.1 U1.40 | length 14.1
  Top Layer w0.2: R19.1 14.327,32.77 14.577,33.02 17.94,36.383 25.72,36.383 26.203,35.9 U1.40
GPIO33: R20.1 U1.41 | length 15.5
  Top Layer w0.2: R20.1 14.327,30.969 15.113,31.755 15.113,33.02 18.126,36.033 25.562,36.033 26.095,35.5 U1.41
GPIO34: R45.1 R54.2 U1.44 | length 49.5
  Top Layer w0.2: R45.1 14.352,45.085 15.748,45.085 v1(16.891,43.942) ; v1(18.161,34.671) 18.634,34.198 24.887,34.198 24.989,34.3 U1.44 ; v1(35.56,50.673) R54.2
  Bottom Layer w0.2: v1(18.161,34.671) 18.161,42.672 v1(16.891,43.942) 16.002,44.831 16.002,48.387 17.907,50.292 30.353,50.292 30.734,50.673 v1(35.56,50.673)
GPIO35: R47.1 R52.2 U1.45 | length 49.6
  Top Layer w0.2: R47.1 14.378,41.402 16.002,41.402 v1(16.891,40.513) ; v1(16.891,33.909) 16.952,33.848 25.031,33.848 25.083,33.9 U1.45 ; v1(33.782,51.943) R52.2
  Bottom Layer w0.2: v1(16.891,33.909) 16.983,34.001 16.983,40.421 v1(16.891,40.513) 15.24,42.164 15.24,48.768 17.495,51.023 29.941,51.023 30.861,51.943 v1(33.782,51.943)
GPIO36: R17.1 U1.46 | length 16.7
  Top Layer w0.2: R17.1 14.327,27.367 14.577,27.617 14.627,27.617 15.748,28.738 15.748,31.75 17.496,33.498 25.176,33.498 25.178,33.5 U1.46
GPIO37: R42.1 U1.47 | length 15.7
  Top Layer w0.2: R42.1 14.362,29.083 v1(15.087,29.083) ; v1(16.637,29.083) 16.637,32.091 17.646,33.1 U1.47
  Bottom Layer w0.2: v1(15.087,29.083) v1@16.51,29.083
GPIO38: R46.2 R53.1 U1.48 | length 54.5
  Top Layer w0.2: R46.2 15.85,43.205 v1(16.891,42.164) ; v1(17.491,32.096) 18.095,32.7 U1.48 ; v1(37.338,51.308) R53.1
  Bottom Layer w0.2: v1(17.491,32.096) 17.491,41.564 v1(16.891,42.164) 15.621,43.434 15.621,48.641 17.653,50.673 30.099,50.673 30.734,51.308 v1(37.338,51.308)
GPIO39: R44.2 R55.1 U1.49 | length 56.2
  Top Layer w0.2: R44.2 15.824,46.914 v1(16.891,45.847) ; v1(18.458,31.92) 18.838,32.3 U1.49 ; v1(40.894,51.943) R55.1
  Bottom Layer w0.2: v1(18.458,31.92) 18.761,32.223 18.761,43.977 v1(16.891,45.847) 16.383,46.355 16.383,48.273 18.021,49.911 30.607,49.911 30.769,50.073 37.373,50.073 39.243,51.943 v1(40.894,51.943)
I2C_SCL: P4.18 R42.2 | length 8.6
  Top Layer w0.2: P4.18 6.548,30.353 11.592,30.353 12.527,29.418 12.577,29.418 12.827,29.168 R42.2
I2C_SDA: P4.17 R17.2 | length 5.8
  Top Layer w0.2: P4.17 7.818,29.083 11.111,29.083 12.827,27.367 R17.2
I_PFC_N: P3.14 R15.2 | length 5.5
  Top Layer w0.3: R15.2 52.197,32.943 52.397,33.143 52.701,33.143 53.721,34.163 57.162,34.163 P3.14
I_PFC_P: P3.15 R14.2 | length 8.4
  Top Layer w0.3: R14.2 52.197,29.641 52.397,29.841 52.636,29.841 53.148,30.353 58.42,30.353 59.682,31.615 P3.15
IU+: C25.1 C28.2 R36.2 U1.1 | length 40.2
  Top Layer w0.2: U1.1 27.208,21.446 36.97,11.684 46.99,11.684 47.498,11.176 v2(47.498,11.049)
  Top Layer w0.3: v2(47.498,11.049) R36.2
  Bottom Layer w0.5: v2(47.498,11.049) 47.51,11.061 48.629,11.061 C28.2 48.653,11.061 50.685,11.061 C25.1
IU-: C28.1 C35.2 R39.2 U1.2 | length 39.6
  Top Layer w0.2: U1.2 27.608,21.541 37.084,12.065 46.863,12.065 47.371,12.573 v2(47.498,12.573) 50.57,12.573 R39.2
  Bottom Layer w0.5: v2(47.498,12.573) C28.1 50.597,12.573 50.697,12.673 C35.2
IUS+: P3.30 R36.1 | length 6.2
  Top Layer w0.3: R36.1 52.197,11.099 52.397,11.299 52.447,11.299 54.983,13.835 P3.30
IUS-: P3.29 R39.1 | length 9.1
  Top Layer w0.3: R39.1 52.197,12.75 52.397,12.95 52.447,12.95 54.61,15.113 58.432,15.113 P3.29
IV+: C26.1 C29.2 R37.2 U1.3 | length 37.1
  Top Layer w0.2: U1.3 28.008,23.046 36.068,14.986 46.99,14.986 47.498,14.478 v2(47.498,14.351) R37.2
  Bottom Layer w0.5: v2(47.498,14.351) 47.51,14.363 48.629,14.363 C29.2 48.653,14.363 50.685,14.363 C26.1
IV-: C29.1 C36.2 R40.2 U1.4 | length 36.5
  Top Layer w0.2: U1.4 28.408,23.141 36.182,15.367 46.99,15.367 v2(47.498,15.875) 50.57,15.875 R40.2
  Bottom Layer w0.5: v2(47.498,15.875) C29.1 50.597,15.875 50.697,15.975 C36.2
IVS+: P3.28 R37.1 | length 5.8
  Top Layer w0.3: R37.1 52.197,14.401 52.397,14.601 52.457,14.601 54.001,16.145 56.94,16.145 P3.28
IVS-: P3.27 R40.1 | length 8.7
  Top Layer w0.3: R40.1 52.197,16.052 52.397,16.252 52.447,16.252 53.724,17.529 58.556,17.529 P3.27
IW+: C27.1 C30.2 R38.2 U1.5 | length 34
  Top Layer w0.2: U1.5 28.808,24.545 35.192,18.161 46.99,18.161 v2(47.498,17.653) R38.2
  Bottom Layer w0.5: v2(47.498,17.653) 47.51,17.665 48.629,17.665 C30.2 48.653,17.665 50.685,17.665 C27.1
IW-: C30.1 C37.2 R41.2 U1.6 | length 33.6
  Top Layer w0.2: U1.6 29.208,24.64 35.306,18.542 46.863,18.542 v2(47.498,19.177) 50.57,19.177 R41.2
  Bottom Layer w0.5: v2(47.498,19.177) C30.1 50.597,19.177 50.697,19.277 C37.2
IWS+: P3.26 R38.1 | length 5.5
  Top Layer w0.3: R38.1 52.197,17.703 52.397,17.903 52.447,17.903 53.34,18.796 57.051,18.796 P3.26
IWS-: P3.25 R41.1 | length 8.4
  Top Layer w0.3: R41.1 52.197,19.354 52.397,19.554 52.447,19.554 53.086,20.193 58.432,20.193 P3.25
NetC5_2: C5.2 R22.1 SW1.1 | length 26.1
  Top Layer w0.3: R22.1 14.327,39.547 14.527,39.747 17.649,39.747 19.05,41.148 C5.2 18.942,52.432 18.942,55.073 18.833,55.181 SW1.1@18.833,61.681
NetJP1_1: JP1.1 R1.2 R3.1 | length 6.3
  Top Layer w0.3: JP1.1 29.464,4.8 30.176,4.088 R3.1 R1.2
NetJP2_1: JP2.1 R2.2 R4.1 | length 6.4
  Top Layer w0.3: R2.2 R4.1 38.945,4.088 39.657,4.8 JP2.1
NetJP3_1: JP3.1 R21.1 | length 3.6
  Top Layer w0.3: JP3.1 48.352,61.175 48.845,60.682 R21.1
NetLED1_A: LED1.A R21.2 | length 2.8
  Top Layer w0.3: R21.2 49.01,59.067 51.447,59.067 LED1.A
NetP1_1: P1.1 R48.2 | length 4.1
  Top Layer w0.3: R48.2 28.448,58.263 P1.1
NetP1_2: P1.2 R49.1 | length 7.3
  Top Layer w0.3: R49.1 26.67,59.025 P1.2
NetP1_3: P1.3 R50.2 | length 4.2
  Top Layer w0.3: P1.3 31.36,58.31 32.004,57.666 R50.2
NetP1_4: P1.4 R51.1 | length 6.9
  Top Layer w0.3: R51.1 30.226,60.041 P1.4
NetP1_6: P1.6 R52.1 | length 7.4
  Top Layer w0.3: R52.1 33.782,56.769 32.639,57.912 32.639,59.914 P1.6
NetP1_7: P1.7 R53.2 | length 4.3
  Top Layer w0.3: P1.7 37.338,57.737 R53.2
NetP1_8: P1.8 R54.1 | length 7.1
  Top Layer w0.3: R54.1 35.56,57.531 35.179,57.912 35.179,59.914 P1.8
NetP1_9: P1.9 R55.2 | length 4.7
  Top Layer w0.3: P1.9 40.894,56.721 R55.2
NetP1_10: P1.10 R56.1 | length 7.5
  Top Layer w0.3: P1.10 37.719,59.914 37.719,58.166 39.116,56.769 R56.1
NetP4_1: P4.1 R44.1 | length 6.1
  Top Layer w0.3: P4.1 10.346,49.395 12.577,47.164 12.627,47.164 12.827,46.964 R44.1
NetP4_2: P4.2 R43.2 | length 8.9
  Top Layer w0.3: P4.2 6.548,50.673 10.922,50.673 12.577,49.018 12.627,49.018 12.827,48.818 R43.2
NetP4_3: P4.3 R46.1 | length 6.6
  Top Layer w0.3: P4.3 9.177,46.855 12.577,43.455 12.627,43.455 12.827,43.255 R46.1
NetP4_4: P4.4 R45.2 | length 9.3
  Top Layer w0.3: P4.4 6.421,48.006 9.931,48.006 12.827,45.11 R45.2
NetP4_6: P4.6 R47.2 | length 8.8
  Top Layer w0.3: P4.6 6.532,43.053 10.922,43.053 12.374,41.601 12.627,41.601 12.827,41.401 R47.2
NetR5_1: R5.1 SW1.2 | length 9.4
  Top Layer w0.3: R5.1 14.291,52.367 14.291,55.139 14.333,55.181 SW1.2@14.333,61.681
NetR23_1: R23.1 U1.37 | length 34.9
  Top Layer w0.2: R23.1 17.676,18.311 20.574,21.209 20.574,23.709 21.376,24.511 v1(22.098,24.511) ; U1.37 28.008,38.354 28.321,38.667 v1(28.321,38.989)
  Bottom Layer w0.2: v1(22.098,24.511) 22.098,24.574 21.844,24.828 21.844,37.338 23.876,39.37 27.877,39.37 28.258,38.989 v1(28.321,38.989)
NetR24_1: R24.1 U1.36 | length 37.8
  Top Layer w0.2: R24.1 17.272,16.51 21.336,20.574 v1(21.336,23.622) ; U1.36 28.408,37.806 29.337,38.735 v1(29.337,39.116)
  Bottom Layer w0.2: v1(21.336,23.622) 21.336,37.338 23.718,39.72 28.733,39.72 v1(29.337,39.116)
NetR25_1: R25.1 U1.35 | length 35.1
  Top Layer w0.2: R25.1 18.611,21.913 19.304,22.606 19.304,24.13 v1(20.701,25.527) ; U1.35 28.808,37.317 30.099,38.608 v1(30.099,39.751)
  Bottom Layer w0.2: v1(20.701,25.527) 20.701,25.625 20.92,25.844 20.92,37.557 23.433,40.07 29.782,40.07 30.099,39.753 v1(30.099,39.751)
PWM_PFC_1: P3.13 R26.2 | length 8.7
  Top Layer w0.3: R26.2 52.197,31.292 52.397,31.492 52.701,31.492 53.975,32.766 58.166,32.766 59.555,34.155 P3.13
RUN: P3.12 R34.2 | length 5.9
  Top Layer w0.3: R34.2 52.197,34.594 52.397,34.794 52.447,34.794 54.348,36.695 P3.12
SPI_CS_CLK: P4.13 R16.2 | length 5.2
  Top Layer w0.2: P4.13 7.876,34.221 12.577,34.221 12.827,34.471 R16.2
SPI_FRM_0: P4.14 R18.2 | length 8.6
  Top Layer w0.2: P4.14 5.27,34.353 6.35,35.433 11.748,35.433 12.345,36.03 12.577,36.03 12.827,36.28 R18.2
SPI_MISO: P4.15 R20.2 | length 5.3
  Top Layer w0.2: P4.15 12.073,31.615 12.469,31.219 12.577,31.219 12.827,30.969 R20.2
SPI_MOSI: P4.16 R19.2 | length 8
  Top Layer w0.2: P4.16 6.375,32.72 R19.2
TRSTn: P4.9 R3.2 R48.1 U1.50 | length 86.4
  Top Layer w0.2: U1.50 26.242,31.9 26.192,31.95 19.377,31.95 18.034,30.607 v1(18.034,29.761) 21.633,26.162 22.606,26.162 23.495,25.273 23.495,12.319 29.926,5.888 29.926,5.838 30.176,5.588 R3.2 ; v1(28.448,51.623) R48.1
  Bottom Layer w0.2: v1(18.034,29.761) 17.8,29.761 8.575,38.986 8.059,38.986 P4.9 9.525,40.95 9.525,49.403 11.745,51.623 v1(28.448,51.623)
UH_IO20: P3.10 R32.2 | length 5.6
  Top Layer w0.3: R32.2 52.197,37.896 52.397,38.096 52.447,38.096 53.467,39.116 57.051,39.116 P3.10
UL_IO21: P3.9 R31.2 | length 8.5
  Top Layer w0.3: R31.2 52.197,39.547 52.397,39.747 52.447,39.747 53.213,40.513 58.432,40.513 P3.9
VCAP12A: C8.2 U1.21 | length 3.3
  Top Layer w0.2: U1.21 33.519,33.9 34.163,34.544 v1(34.544,34.544)
  Bottom Layer w0.2: v1(34.544,34.544) 34.544,34.637 34.753,34.846 C8.2
VCAP12B: C1.2 U1.43 | length 3.2
  Top Layer w0.2: v1(24.638,34.798) 24.746,34.798 24.844,34.7 U1.43
  Bottom Layer w0.2: C1.2 24.487,34.539 24.638,34.69 v1(24.638,34.798)
VH_IO22: P3.8 R30.2 | length 5.3
  Top Layer w0.3: R30.2 52.197,41.198 52.397,41.398 52.447,41.398 52.824,41.775 P3.8
VL_IO23: P3.7 R29.2 | length 8.2
  Top Layer w0.3: R29.2 52.197,42.849 52.397,43.049 52.569,43.049 52.573,43.053 58.432,43.053 P3.7
VOLT_U: C16.2 P3.19 R10.2 | length 9.7
  Top Layer w0.3: R10.2 52.197,26.339 52.397,26.539 52.454,26.482 v1(53.147,26.482) 54.479,27.813 58.432,27.813 P3.19
  Bottom Layer w0.3: v1(53.147,26.482) 54.036,26.482 C16.2
VOLT_V: C20.2 P3.20 R12.2 | length 6.9
  Top Layer w0.3: R12.2 52.197,24.688 52.397,24.888 52.955,24.888 54.602,26.535 P3.20
  Bottom Layer w0.3: v1(53.086,24.892) 53.167,24.892 53.252,24.807 53.909,24.807 C20.2
VOLT_W: P3.22 R8.2 | length 6.1
  Top Layer w0.3: R8.2 52.197,21.386 52.397,21.586 52.447,21.586 54.856,23.995 P3.22
VSP: P3.21 R9.2 | length 9.1
  Top Layer w0.3: R9.2 52.197,23.037 52.397,23.237 52.574,23.237 54.61,25.273 58.547,25.273 59.71,24.11 P3.21
WH_IO24: P3.6 R28.2 | length 5
  Top Layer w0.3: R28.2 52.265,44.382 57.102,44.382 P3.6
WL_IO25: P3.5 R27.2 | length 8.3
  Top Layer w0.3: R27.2 52.197,46.051 52.397,45.851 52.447,45.851 52.705,45.593 58.432,45.593 P3.5
XIN: C9.2 P2.1 XT1.1 | length 6.6
  Bottom Layer w0.5: P2.1 39.6,30.61 39.6,30.964 40.992,32.356 41.429,32.356 C9.2 42.923,32.456 43.824,31.555 XT1.1
XIO: C10.2 P2.4 XT1.2 | length 6.8
  Bottom Layer w0.5: P2.4 39.291,37.539 39.291,37.036 40.826,35.501 41.429,35.501 C10.2 41.561,35.433 42.974,35.433 XT1.2
XRSTn: P4.7 R22.2 R50.1 U1.51 | length 59.1
  Top Layer w0.2: v1(20.32,31.3) 20.397,31.377 20.518,31.377 20.642,31.5 U1.51 ; v1(31.877,49.022) 31.877,53.086 R50.1
  Top Layer w0.3: P4.7 10.295,41.775 12.323,39.747 12.627,39.747 12.827,39.547 R22.2 v1(12.827,38.735)
  Bottom Layer w0.2: v1(12.827,38.735) 12.827,35.56 17.78,30.607 19.731,30.607 20.083,30.958 20.083,30.983 20.32,31.22 v1(20.32,31.3) 20.32,47.879 21.463,49.022 v1(31.877,49.022)
pads on no net: P1.5 P4.5 U1.13 U1.26 U1.31
copper on no net:
  other v4: 4,4 61,4 4,62.5 61,62.5

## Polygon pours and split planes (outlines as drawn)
GND on Top Layer "NONET_L01_P-001" (solid, remove dead copper, pour order 0): -1.016,67.056 65.913,67.056 65.913,-0.381 -1.143,-0.381
GND on Bottom Layer "NONET_L01_P-001" (solid, remove dead copper, pour order 1): -1.016,67.056 65.913,67.056 65.913,-0.381 -1.143,-0.381

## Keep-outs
Keep-Out Layer:
  circle w0.1: c4,4 r2
  circle w0.1: c61,4 r2
  circle w0.1: c61,62.5 r2
  circle w0.1: c4,62.5 r2
  lines w0.1: 0,1.905 0,64.516 ; 0,2 ccw(c2,2) 2,0 ; 0,64.5 cw(c2,64.5) 2,66.5 ; 1.905,0 62.992,0 ; 1.984,66.5 63.04,66.5 ; 63,0 ccw(c63,2) 65,2 ; 63,66.5 cw(c63,64.5) 65,64.5 ; 65,2.008 65,64.54

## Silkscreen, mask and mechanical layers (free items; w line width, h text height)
Top Overlay:
  lines w0.1: 0.127,23.241 8.636,23.241 ; 0.127,25.654 8.636,25.654 ; 0.254,35.687 8.636,35.687 ; 8.128,41.148 9.017,41.148 ; 8.636,38.989 10.541,38.989 ; 28.321,56.769 28.321,58.674 ; 34.036,56.515 34.036,58.42 ; 39.243,56.642 39.243,58.928 ; 56.261,45.847 64.77,45.847 ; 56.388,48.387 64.008,48.387
  text "GND" at 31.904,62.838 h1 r90
  text "DVDD" at 29.237,62.711 h1 r90
  text "IO35" at 34.444,62.711 h1 r90
  text "IO34" at 36.984,62.711 h1 r90
  text "BOOT" at 39.524,62.711 h1 r90
  text "LED" at 43.969,60.425 h1 r90
  text "IO30" at 43.969,56.742 h1 r90
  text "XRSTn" at 13.235,56.488 h1 r90
  text "XRSTn" at 29.056,56.234 h1
  text "IO38" at 35.152,56.234 h1
  text "TRSTn" at 25.119,55.599 h1
  text "NC" at 33.182,55.487 h1
  text "IO39" at 38.138,55.487 h1
  text "IO40" at 1.2,48.995 h1
  text "IO39" at 8.863,48.995 h1
  text "GND" at 60.806,48.868 h1
  text "GND" at 55.78,48.233 h1 r90
  text "IO34" at 1.152,46.455 h1
  text "IO38" at 8.863,46.455 h1
  text "3.3VIN" at 60.806,46.328 h1
  text "IO35" at 1.2,43.915 h1
  text "NC" at 8.863,43.915 h1
  text "IO24" at 53.19,43.788 h1
  text "IO25" at 60.806,43.788 h1
  text "GND" at 1.409,41.375 h1
  text "IO22" at 53.237,41.248 h1
  text "IO23" at 60.806,41.248 h1
  text "XRSTn" at 10.187,39.47 h1 r90
  text "DVDD" at 0.624,38.835 h1
  text "IO20" at 53.237,38.708 h1
  text "IO21" at 60.806,38.708 h1
  text "TRSTn" at 11.711,37.057 h1 r90
  text "GND" at 1.37,36.168 h1
  text "IO18" at 53.394,36.168 h1
  text "IO19" at 60.806,36.168 h1
  text "IO37" at 1.2,33.755 h1
  text "AD15" at 52.947,33.693 h1
  text "IO36" at 8.99,33.628 h1
  text "IO26" at 60.806,33.628 h1
  text "IO39" at 1.247,31.215 h1
  text "IO38" at 8.99,31.088 h1
  text "GND" at 53.447,31.088 h1
  text "AD14" at 60.679,31.088 h1
  text "IO30" at 1.2,28.675 h1
  text "IO29" at 8.99,28.548 h1
  text "AD6" at 53.494,28.548 h1
  text "GND" at 60.806,28.548 h1
  text "3.3VIN" at 0.1,26.135 h1
  text "AD12" at 53.059,26.008 h1
  text "AD10" at 60.679,26.008 h1
  text "GND" at 1.409,23.595 h1
  text "AD8" at 53.447,23.468 h1
  text "AD9" at 60.806,23.468 h1
  text "AD11" at 1.105,21.055 h1
  text "AD13" at 8.99,20.928 h1
  text "GND" at 53.447,20.928 h1
  text "GND" at 60.806,20.928 h1
  text "IO27" at 1.2,18.515 h1
  text "AD7" at 8.99,18.388 h1
  text "AD4" at 53.399,18.388 h1
  text "AD5" at 60.806,18.388 h1
  text "IO29" at 1.247,15.975 h1
  text "IO28" at 8.99,15.848 h1
  text "AD2" at 53.447,15.848 h1
  text "AD3" at 60.806,15.848 h1
  text "EVB_SPC1168QFN52_A_0001" at 14.501,13.477 h1.5
  text "GND" at 1.409,13.435 h1
  text "GND" at 8.99,13.308 h1
  text "AD0" at 53.447,13.308 h1
  text "AD1" at 60.806,13.308 h1
  text "GND" at 17.118,1.751 h1
  text "DVDD" at 24.103,1.751 h1
  text "DVDD" at 38.708,1.751 h1
  text "GND" at 46.582,1.751 h1
Mechanical 1:
  circle w0.1: c4,4 r2
  circle w0.1: c61,4 r2
  circle w0.1: c61,62.5 r2
  circle w0.1: c4,62.5 r2
  lines w0.1: 0,2 ccw(c2,2) 2,0 ; 0,2.032 0,64.5 cw(c2,64.5) 2,66.5 63,66.5 cw(c63,64.5) 65,64.5 65,2.008 ; 2.032,0 62.992,0 ; 63,0 ccw(c63,2) 65,2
